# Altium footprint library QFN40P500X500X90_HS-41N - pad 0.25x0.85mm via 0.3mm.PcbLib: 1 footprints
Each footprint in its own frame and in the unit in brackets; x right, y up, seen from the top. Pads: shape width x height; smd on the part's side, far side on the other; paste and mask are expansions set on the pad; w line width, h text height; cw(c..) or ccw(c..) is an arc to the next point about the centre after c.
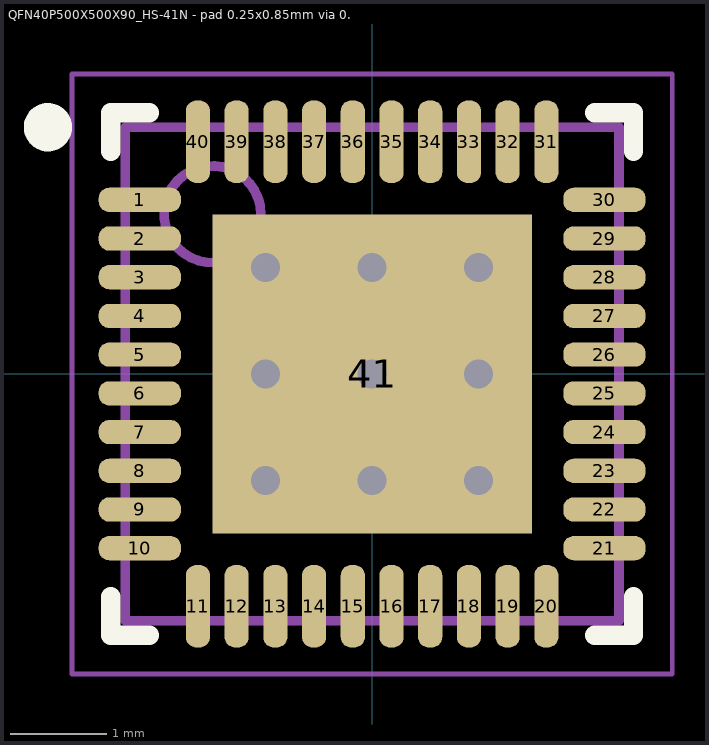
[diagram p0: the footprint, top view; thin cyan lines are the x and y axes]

## QFN40P500X500X90_HS-41N - pad 0.25x0.85mm via 0.3mm [mm] "QFN, 40-Leads, Body 5.00x5.00mm, Pitch 0.40mm, Thermal Pad 3.30x3.30mm, IPC Medium Density"
height 0.9
pads (41):
  rrect85% 0.85x0.25 smd: 1(-2.4,1.8) 2(-2.4,1.4) 3(-2.4,1) 4(-2.4,0.6) 5(-2.4,0.2) 6(-2.4,-0.2) 7(-2.4,-0.6) 8(-2.4,-1) 9(-2.4,-1.4) 10(-2.4,-1.8) 21(2.4,-1.8) 22(2.4,-1.4) 23(2.4,-1) 24(2.4,-0.6) 25(2.4,-0.2) 26(2.4,0.2) 27(2.4,0.6) 28(2.4,1) 29(2.4,1.4) 30(2.4,1.8)
  rrect85% 0.25x0.85 smd: 11(-1.8,-2.4) 12(-1.4,-2.4) 13(-1,-2.4) 14(-0.6,-2.4) 15(-0.2,-2.4) 16(0.2,-2.4) 17(0.6,-2.4) 18(1,-2.4) 19(1.4,-2.4) 20(1.8,-2.4) 31(1.8,2.4) 32(1.4,2.4) 33(1,2.4) 34(0.6,2.4) 35(0.2,2.4) 36(-0.2,2.4) 37(-0.6,2.4) 38(-1,2.4) 39(-1.4,2.4) 40(-1.8,2.4)
  rect 3.3x3.3 smd: 41(0,0)
via 1.1,-1.1 diameter 0.7 hole 0.3
via 0,-1.1 diameter 0.7 hole 0.3
via -1.1,-1.1 diameter 0.7 hole 0.3
via 1.1,0 diameter 0.7 hole 0.3
via 0,0 diameter 0.7 hole 0.3
via -1.1,0 diameter 0.7 hole 0.3
via 1.1,1.1 diameter 0.7 hole 0.3
via 0,1.1 diameter 0.7 hole 0.3
via -1.1,1.1 diameter 0.7 hole 0.3
Top Overlay:
  circle w0.25: c-3.35,2.55 r0.125
  lines w0.2: -2.7,-2.3 -2.7,-2.7 -2.3,-2.7 ; -2.7,2.3 -2.7,2.7 -2.3,2.7 ; 2.3,-2.7 2.7,-2.7 2.7,-2.3 ; 2.3,2.7 2.7,2.7 2.7,2.3
Mechanical 13:
  circle w0.1: c-1.65,1.65 r0.5
  lines w0.1: -2.55,-2.55 2.55,-2.55 2.55,2.55 -2.55,2.55 -2.55,-2.55
Mechanical 15:
  lines w0.05: -3.1,-3.1 3.1,-3.1 3.1,3.1 -3.1,3.1 -3.1,-3.1
  lines w0.1: -0.5,0 0.5,0 ; 0,-0.5 0,0.5
3D body "QFN40P500X500X90_HS-41N.step": height 1, standoff 0.1, extent -2.551,-2.551 2.551,2.551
